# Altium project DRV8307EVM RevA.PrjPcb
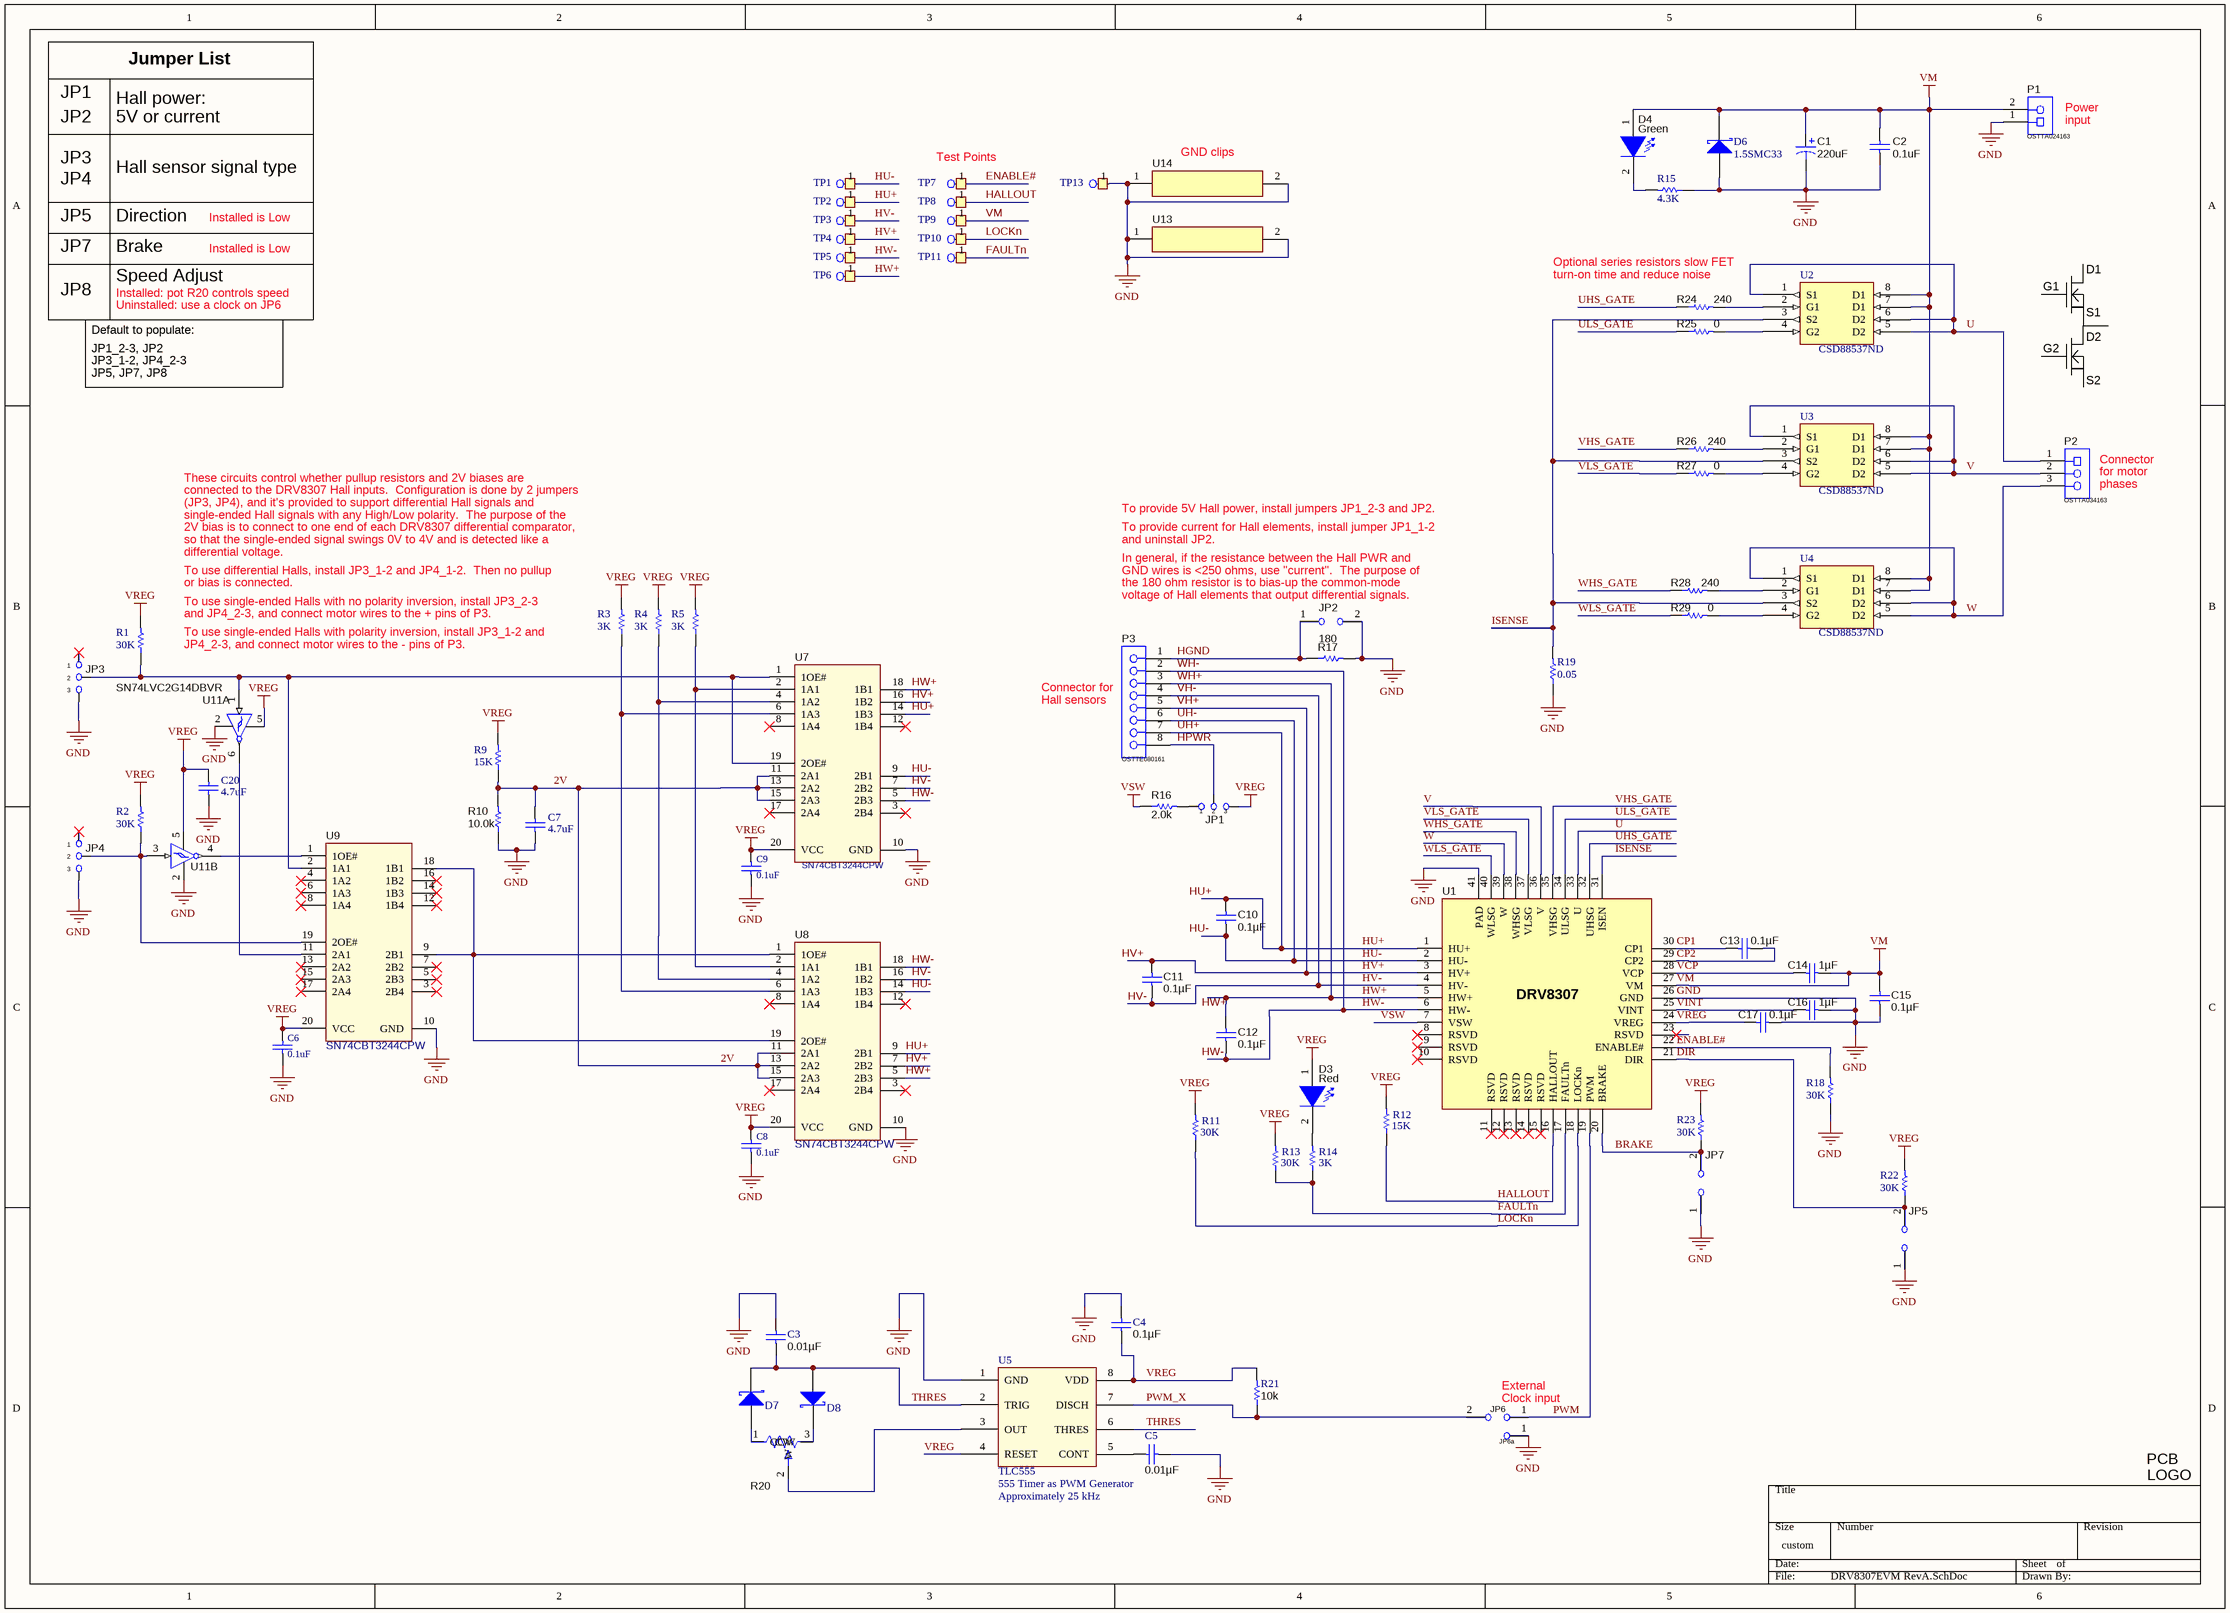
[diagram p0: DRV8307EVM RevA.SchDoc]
CopyrightYear: 2012; PCB_Layout: Who did the Layout?; PCB_Rev: E1; PRJ_Customer: Public Release; PRJ_Engineer: Enter name of project lead; PRJ_Number: XX####; PRJ_Title: Change in menu Project|Project Options|Parameters; SCH_Rev: E1; TechSupport: http://www.ti.com/support
1 sheet, 84 parts. Net scope: global (net labels, ports and power ports of the same name join across sheets).
Board file: DRV8307EVM RevA.PcbDoc

## Sheet DRV8307EVM RevA.SchDoc
size 457 x 330 mm

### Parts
C1  220uF  [UVZ1J221MPD_fp]
C2  ValueDisplayed: 0.1uF  [0805L]  (hidden comment: 06031C272JAT2A)
C3  ValueDisplayed: 0.01µF  [0805L]  (hidden comment: GRM155R61A103KA01D)
C4  ValueDisplayed: 0.1µF  [0805L]  (hidden comment: C1005X5R1A104K)
C5  ValueDisplayed: 0.01µF  [0805L]  (hidden comment: GRM155R61A103KA01D)
C6  value 0.1uF  [0805L]  (hidden comment: Cap)
C7  value 4.7uF  [0805L]
C8  value 0.1uF  [0805L]  (hidden comment: Cap)
C9  value 0.1uF  [0805L]  (hidden comment: Cap)
C10  ValueDisplayed: 0.1µF  [0805L]  (hidden comment: C0805C104K5RACTU)
C11  ValueDisplayed: 0.1µF  [0805L]  (hidden comment: C0805C104K5RACTU)
C12  ValueDisplayed: 0.1µF  [0805L]  (hidden comment: C0805C104K5RACTU)
C13  ValueDisplayed: 0.1µF  [0805L]  (hidden comment: C0805C104K5RACTU)
C14  ValueDisplayed: 1µF  [0805L]  (hidden comment: C0805C104K5RACTU)
C15  ValueDisplayed: 0.1µF  [0805L]  (hidden comment: C0805C104K5RACTU)
C16  ValueDisplayed: 1µF  [0805L]  (hidden comment: C0805C104K5RACTU)
C17  ValueDisplayed: 0.1µF  [0805L]  (hidden comment: C0805C104K5RACTU)
C20  value 4.7uF  [0805L]
D3  value Red  [LED_LTST-C170]  (hidden comment: LTST-C170KRKT)
D4  value Green  [LED_LTST-C171]  (hidden comment: LTST-C171GKT)
D6  1.5SMC33  [SMC-W]
D7  MBRA210LT3G  [SMA]  (value not drawn)
D8  MBRA210LT3G  [SMA]  (value not drawn)
JP1  Pin1: 1  Pin2: 2  Pin3: 3  [HDR100_1X3]  (hidden comment: JUMPER_3X100MIL)
JP2  JUMPER_2X100MIL  [2PIN HEADER]  (value not drawn)
JP3  Pin1: 1  Pin2: 2  Pin3: 3  [HDR100_1X3]  (hidden comment: JUMPER_3X100MIL)
JP4  Pin1: 1  Pin2: 2  Pin3: 3  [HDR100_1X3]  (hidden comment: JUMPER_3X100MIL)
JP5  (no value)  [HDR100_1X2]
JP6  (no value)  [HDR100_1X2]
JP6a  (no value)  [1x1 Header]
JP7  (no value)  [HDR100_1X2]
LOGO  Texas Instruments  [TI_Stacked_Overlay_Medium]  (value not drawn)  (no BOM)
P1  OSTTA024163  [On-Shore_OSTTA024163]
P2  OSTTA034163  [On-Shore_OSTTA034163]
P3  OSTTE080161  [On-Shore_OSTTE080161]
R1  value 30K  [0805L]
R2  value 30K  [0805L]
R3  value 3K  [0805L]
R4  value 3K  [0805L]
R5  value 3K  [0805L]
R9  value 15K  [0805L]
R10  value 10.0k  [0805L]  (hidden comment: RT0805BRD0710KL)
R11  30K  [0805l]
R12  15K  [0805L]
R13  30K  [0805L]
R14  3K  [0805L]
R15  value 4.3K  [0805L]  (hidden comment: Res1)
R16  value 2.0k  [0805_HV]  (hidden comment: ERJ-6GEYJ202V)
R17  value 180  [0805L]  (hidden comment: CRCW0805180RJNEA)
R18  value 30K  [0805L]
R19  value 0.05  [2512M]
R20  3352T-1-502LF  [3352_Trimmer_Pot]  (value not drawn)
R21  value 10k  [0805L]  (hidden comment: CRCW040210K0JNED)
R22  value 30K  [0805L]
R23  value 30K  [0805L]
R24  value 240  [0603L]  (hidden comment: RC0603FR-07240RL)
R25  value 0  [0603L]  (hidden comment: RC0603FR-07240RL)
R26  value 240  [0603L]  (hidden comment: RC0603FR-07240RL)
R27  value 0  [0603L]  (hidden comment: RC0603FR-07240RL)
R28  value 240  [0603L]  (hidden comment: RC0603FR-07240RL)
R29  value 0  [0603L]  (hidden comment: RC0603FR-07240RL)
TP1  TP-LOOP-ORANGE  [TEST POINT 0.052]  (value not drawn)
TP2  TP-LOOP-ORANGE  [TEST POINT 0.052]  (value not drawn)
TP3  TP-LOOP-ORANGE  [TEST POINT 0.052]  (value not drawn)
TP4  TP-LOOP-ORANGE  [TEST POINT 0.052]  (value not drawn)
TP5  TP-LOOP-ORANGE  [TEST POINT 0.052]  (value not drawn)
TP6  TP-LOOP-ORANGE  [TEST POINT 0.052]  (value not drawn)
TP7  TP-LOOP-ORANGE  [TEST POINT 0.052]  (value not drawn)
TP8  TP-LOOP-ORANGE  [TEST POINT 0.052]  (value not drawn)
TP9  TP-LOOP-ORANGE  [TEST POINT 0.052]  (value not drawn)
TP10  TP-LOOP-BLACK  [TEST POINT 0.052]  (value not drawn)
TP11  TP-LOOP-ORANGE  [TEST POINT 0.052]  (value not drawn)
TP13  TP-LOOP-BLACK  [TEST POINT 0.052]  (value not drawn)
U1  DRV8307  [RHA0040A]
U2  CSD88537ND  [SO-8_N]
U3  CSD88537ND  [SO-8_N]
U4  CSD88537ND  [SO-8_N]
U5  TLC555  [SOIC127P600X175-8N]
U7  SN74CBT3244CPW  [PW0020A_N]
U8  SN74CBT3244CPW  [PW0020A_N]
U9  SN74CBT3244CPW  [PW0020A_N]
U11  SN74LVC2G14DBVR  [DBV0006A_N]  (parts A,B of 2)
U13  (no value)  [GND_Bridge]
U14  (no value)  [GND_Bridge]

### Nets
GND: C1.2(-) C2.2 C3.1 C4.1 C5.2 C6.1 C7.2 C8.1 C9.1 C15.2 C16.1 C17.1 C20.2 D6.1(A) JP2.2 JP3.3 JP4.3 JP5.1 JP6a.1 JP7.1 P1.1 R10.1 R15.1 R17.2 R18.1 R19.1 TP13.1 U1.26(GND) U1.41(PAD) U5.1(GND) U7.10(GND) U8.10(GND) U9.10(GND) U11.2(GND) U13.1(GND) U13.2(GND) U14.1(GND) U14.2(GND)
VM: C1.1(+) C2.1 C14.1 C15.1 D4.1(A) D6.2(K) P1.2 TP9.1 U1.27(VM) U2.7(D1) U2.8(D1) U3.7(D1) U3.8(D1) U4.7(D1) U4.8(D1)
VREG: C4.2 C6.2 C8.2 C9.2 C17.2 C20.1 D3.1(A) JP1.3 R1.2 R2.2 R3.2 R4.2 R5.2 R9.2 R11.2 R12.2 R13.2 R21.2 R22.2 R23.2 U1.24(VREG) U5.4(RESET) U5.8(VDD) U7.20(VCC) U8.20(VCC) U9.20(VCC) U11.5(VCC)
VSW: R16.1 U1.7(VSW)
2V: C7.1 R9.1 R10.2 U7.11(2A1) U7.13(2A2) U7.15(2A3) U8.11(2A1) U8.13(2A2) U8.15(2A3)
BRAKE: JP7.2 R23.1 U1.20(BRAKE)
CP1: C13.2 U1.30(CP1)
CP2: C13.1 U1.29(CP2)
DIR: JP5.2 R22.1 U1.21(DIR)
ENABLE#: R18.2 TP7.1 U1.22(ENABLE#)
FAULTn: R13.1 R14.1 TP11.1 U1.17(FAULTn)
HALLOUT: R12.1 TP8.1 U1.16(HALLOUT)
HGND: JP2.1 P3.1 R17.1
HPWR: JP1.2 P3.8
HU+: C10.1 P3.7 TP2.1 U1.1(HU+) U7.14(1B3) U8.9(2B1)  [also labelled UH+]
HU-: C10.2 P3.6 TP1.1 U1.2(HU-) U7.9(2B1) U8.14(1B3)  [also labelled UH-]
HV+: C11.1 P3.5 TP4.1 U1.3(HV+) U7.16(1B2) U8.7(2B2)  [also labelled VH+]
HV-: C11.2 P3.4 TP3.1 U1.4(HV-) U7.7(2B2) U8.16(1B2)  [also labelled VH-]
HW+: C12.1 P3.3 TP6.1 U1.5(HW+) U7.18(1B1) U8.5(2B3)  [also labelled WH+]
HW-: C12.2 P3.2 TP5.1 U1.6(HW-) U7.5(2B3) U8.18(1B1)  [also labelled WH-]
ISENSE: R19.2 U1.31(ISEN) U2.3(S2) U3.3(S2) U4.3(S2)
LOCKn: R11.1 TP10.1 U1.18(LOCKn)
PWM: JP6.1 U1.19(PWM)
PWM_X: JP6.2 R21.1 U5.7(DISCH)
THRES: C3.2 D7.1(K) D8.2(A) U5.2(TRIG) U5.6(THRES)
U: P2.1 U1.33(U) U2.1(S1) U2.5(D2) U2.6(D2)
UHS_GATE: R24.1 U1.32(UHSG)
ULS_GATE: R25.1 U1.34(ULSG)
V: P2.2 U1.36(V) U3.1(S1) U3.5(D2) U3.6(D2)
VCP: C14.2 U1.28(VCP)
VHS_GATE: R26.1 U1.35(VHSG)
VINT: C16.2 U1.25(VINT)
VLS_GATE: R27.1 U1.37(VLSG)
W: P2.3 U1.39(W) U4.1(S1) U4.5(D2) U4.6(D2)
WHS_GATE: R28.1 U1.38(WHSG)
WLS_GATE: R29.1 U1.40(WLSG)
NetC5_1: C5.1 U5.5(CONT)
NetD3_2: D3.2(K) R14.2
NetD4_2: D4.2(K) R15.2
NetD7_2: D7.2(A) R20.1(CCW)
NetD8_1: D8.1(K) R20.3(CW)
NetJP1_1: JP1.1 R16.2
NetJP3_2: JP3.2 R1.1 U7.1(1OE#) U7.19(2OE#) U9.2(1A1) U11.1(1A)
NetJP4_2: JP4.2 R2.1 U9.19(2OE#) U11.3(2A)
NetR3_1: R3.1 U7.6(1A3) U8.6(1A3)
NetR4_1: R4.1 U7.4(1A2) U8.4(1A2)
NetR5_1: R5.1 U7.2(1A1) U8.2(1A1)
NetR20_2: R20.2(W) U5.3(OUT)
NetR24_2: R24.2 U2.2(G1)
NetR25_2: R25.2 U2.4(G2)
NetR26_2: R26.2 U3.2(G1)
NetR27_2: R27.2 U3.4(G2)
NetR28_2: R28.2 U4.2(G1)
NetR29_2: R29.2 U4.4(G2)
NetU8_1: U8.1(1OE#) U8.19(2OE#) U9.9(2B1) U9.18(1B1)
NetU9_1: U9.1(1OE#) U11.4(2Y)
NetU9_11: U9.11(2A1) U11.6(1Y)

Not connected (* = marked no-connect by the designer): JP3 1*; JP4 1*; U1 8(RSVD)* 9(RSVD)* 10(RSVD)* 11(RSVD)* 12(RSVD)* 13(RSVD)* 14(RSVD)* 15(RSVD)* 23(RSVD)*; U7 3(2B4)* 8(1A4)* 12(1B4)* 17(2A4)*; U8 3(2B4)* 8(1A4)* 12(1B4)* 17(2A4)*; U9 3(2B4)* 4(1A2)* 5(2B3)* 6(1A3)* 7(2B2)* 8(1A4)* 12(1B4)* 13(2A2)* 14(1B3)* 15(2A3)* 16(1B2)* 17(2A4)*

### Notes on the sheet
- Jumper List
- JP1
- JP2
- Hall power:
- 5V or current
- (near P1) Power
- (near P1) input
- JP3
- JP4
- Hall sensor signal type
- (near TP7) Test Points
- (near U14) GND clips
- JP5
- JP7
- Direction
- Brake
- Installed is Low
- Optional series resistors slow FET
- (near R24) turn-on time and reduce noise
- D1
- JP8
- Default to populate:
- Speed Adjust
- Installed: pot R20 controls speed
- Uninstalled: use a clock on JP6
- G1
- S1
- JP1_2-3, JP2
- JP3_1-2, JP4_2-3
- JP5, JP7, JP8
- G2
- D2
- S2
- These circuits control whether pullup resistors and 2V biases are
- connected to the DRV8307 Hall inputs.  Configuration is done by 2 jumpers
- (JP3, JP4), and it's provided to support differential Hall signals and
- single-ended Hall signals with any High/Low polarity.  The purpose of the
- To provide 5V Hall power, install jumpers JP1_2-3 and JP2.
- (near P2) Connector
- (near P2) for motor
- (near P2) phases
- 2V bias is to connect to one end of each DRV8307 differential comparator,
- so that the single-ended signal swings 0V to 4V and is detected like a
- differential voltage.
- (near R3) To use differential Halls, install JP3_1-2 and JP4_1-2.  Then no pullup
- To provide current for Hall elements, install jumper JP1_1-2
- and uninstall JP2.
- In general, if the resistance between the Hall PWR and
- (near JP2) GND wires is <250 ohms, use "current".  The purpose of
- or bias is connected.
- (near R3) To use single-ended Halls with no polarity inversion, install JP3_2-3
- (near R1) and JP4_2-3, and connect motor wires to the + pins of P3.
- (near R3) To use single-ended Halls with polarity inversion, install JP3_1-2 and
- JP4_2-3, and connect motor wires to the - pins of P3.
- (near JP2) the 180 ohm resistor is to bias-up the common-mode
- (near JP2) voltage of Hall elements that output differential signals.
- (near P3) Connector for
- (near P3) Hall sensors
- (near JP6) External
- (near JP6) Clock input
- 555 Timer as PWM Generator
- Approximately 25 kHz
- Labels drawn without touching a wire or pin: HU+, HU-, HV+, HW+, HW-

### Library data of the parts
C1 = UVZ1J221MPD: SymbolVersion: use current date i.e. 2008-05-20; SymbolCreator: Use a-id; CompType: Used in some BOM reports.  Useful for finding later.; U/M: EA, IN, or GM
C2 = 06031C272JAT2A: CAP, CERM, 2700pF, 100V, +/-5%, X7R, 0603; Manufacturer: AVX; Polarized: N; CompType: Capacitor; U/M: EA; Cap_F: 0.0000000027; Tolerance_%: 5; ESR_Ohm: 0.174; Value1: 0.174 ohm; VDC_V: 100; TaMin_C: -55; TaMax_C: 125; Cap_Case: 0603
C3 C5 = GRM155R61A103KA01D: CAP, CERM, 0.01uF, 10V, +/-10%, X5R, 0402; Manufacturer: MuRata; Polarized: N; CompType: Capacitor; U/M: EA; Cap_F: 0.00000001; Tolerance_%: 10; Value1: Unknown; TaMin_C: -55; TaMax_C: 85; Cap_Case: 0402
C4 = C1005X5R1A104K: CAP, CERM, 0.1uF, 10V, +/-10%, X5R, 0402; Manufacturer: TDK; Polarized: N; CompType: Capacitor; U/M: EA; Cap_F: 0.0000001; Tolerance_%: 10; ESR_Ohm: 0.0186; Value1: 0.0186 ohm; TaMin_C: -55; TaMax_C: 85; Cap_Case: 0402
C6-C9 C20 = Cap: Capacitor
C10-C17 = C0805C104K5RACTU: CAP, CERM, 0.1uF, 50V, +/-10%, X7R, 0805; Manufacturer: Kemet; Polarized: N; CompType: Capacitor; U/M: EA; Cap_F: 0.0000001; Tolerance_%: 10; ESR_Ohm: 0.064; Value1: 0.064 ohm; VDC_V: 50; IRMS_A: 1.64; TaMin_C: -55; TaMax_C: 125; Cap_Case: 0805
D3 = LTST-C170KRKT: LED, Red, SMD; Manufacturer: Lite-On; Type: AlInGaP; Vf_V: 2; Value2: 2V; Io_A: 20; Value1: W; U/M: EA
D4 = LTST-C171GKT: LED, Green, SMD; Manufacturer: Lite-On; Type: AlInGaP; Vf_V: 2.1; Value2: 2.1V; Io_A: 20; Value1: W; U/M: EA
D6 = D Schottky: Schottky Diode
D7 D8 = MBRA210LT3G: Diode, Schottky, 10V, 2A, SMA; Manufacturer: ON Semiconductor; U/M: EA; Vf_V: 0.35; Value2: 0.35V; Io_A: 2; Vr_V: 10; TJmax_C: 125; RJC_CperW: 22
JP1 JP3 JP4 = JUMPER_3X100MIL: Header, Male 3-pin, 100mil spacing,
JP2 = JUMPER_2X100MIL: Header, Male 2-pin, 100mil spacing,
JP5-JP7 = JUMPER_2X100MIL: Header, Male 2-pin, 100mil spacing,; Manufacturer: Sullins; PartNumber: PEC02SAAN; area: 20000; Value: PEC02SAAN
JP6a = 1x1 Header
LOGO = TI_Logo: Texas Instrument Corporate Signature; SymbolCreator: a0412235
P1 = OSTTA024163: Terminal Block, 2x1, 5.08mm, TH; Manufacturer: On-Shore Technology; SymbolCreator: a0412235; U/M: EA
P2 = OSTTA034163: Terminal Block, 3x1, 5.08 mm, TH; Manufacturer: On-Shore Technology; SymbolCreator: a0412235; U/M: EA
P3 = OSTTE080161: Terminal Block, 8x1, 3.5mm, TH; Manufacturer: On-Shore Technology; SymbolCreator: a0411947; U/M: EA
R1-R5 R9 R11-R15 R18 R22 R23 = Res1: Resistor
R10 = RT0805BRD0710KL: RES, 10.0k ohm, 0.1%, 0.125W, 0805; Manufacturer: Yageo America; CompType: Resistor; Res_ohm: 10000; Value_Code: 10k0; Tolerance_%: 0.1; Power_W: 0.125; VDC_V: 150; TempCo: 25 ppm/C; EIA_Code: E192; U/M: EA
R16 = ERJ-6GEYJ202V: RES, 2.0k ohm, 5%, 0.125W, 0805; Manufacturer: Panasonic; CompType: Resistor; Res_ohm: 2000; Value_Code: 2k00; Tolerance_%: 5; Power_W: 0.125; VDC_V: 150; TempCo: 200 ppm/C; EIA_Code: E24; U/M: EA
R17 = CRCW0805180RJNEA: RES, 180 ohm, 5%, 0.125W, 0805; Manufacturer: Vishay-Dale; CompType: Resistor; Value_Code: 180R; Tolerance_%: 5; Power_W: 0.125; VDC_V: 150; TempCo: 200 ppm/C; EIA_Code: E24; U/M: EA
R19 = CSRN2512FK30L0: RES, 0.03 ohm, 1%, 2W, 2512
R20 = POT_3352P: Potentiometer, 3/8 Cermet, SingleTurn, Flat; Manufacturer: Bourns; Area: 144375; Value: {Value}
R21 = CRCW040210K0JNED: RES, 10k ohm, 5%, 0.063W, 0402; Manufacturer: Vishay-Dale; CompType: Resistor; Res_ohm: 10000; Value_Code: 10k0; Tolerance_%: 5; Power_W: 0.063; VDC_V: 50; TempCo: 200 ppm/C; EIA_Code: E24; U/M: EA
R24 R26 R28 = RC0603FR-07240RL: RES, 240 ohm, 1%, 0.1W, 0603; Manufacturer: Yageo America; CompType: Resistor; Value_Code: 240R; Tolerance_%: 1; Power_W: 0.1; VDC_V: 150; TempCo: 200 ppm/C; U/M: EA
R25 R27 R29 = RC0603FR-07240RL: RES, 240 ohm, 1%, 0.1W, 0603; Manufacturer: Yageo America; CompType: Resistor; Res_ohm: 240; Value_Code: 240R; Tolerance_%: 1; Power_W: 0.1; VDC_V: 150; TempCo: 200 ppm/C; U/M: EA
TP1-TP11 TP13 = TEST POINT: Glass Beaded Test Point
U1 = DRV8308
U2-U4 = FDS8949: MOSFET N-CH DUAL 30V 3.5A SOP8
U5 = TLC555: IC OSC MONO TIMING 2.1MHZ 8-SOIC; Manufacturer: Texas Instruments; MFG Part Number: TLC555QDR; Value: 555 Timer
U8 U9 = SN74CBT3244CPW: Manufacturer: Texas Instruments; SymbolVersion: use current date i.e. 2008-05-20; SymbolCreator: Use a-id; U/M: EA, IN, or GM
U11 = SN74LVC2G14IDBVRQ1: DUAL SCHMITT-TRIGGER INVERTER, DBV0006A; Alternate Manufacturer: None; Manufacturer: Texas Instruments; SymbolCreator: a0411947; CompType: IC; U/M: EA
U13 U14 = GND_Bridge: Manufacturer: Used in BOM report; SymbolVersion: use current date i.e. 2008-05-20; SymbolCreator: Use a-id; CompType: Used in some BOM reports.  Useful for finding later.; U/M: EA, IN, or GM

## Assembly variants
001: all parts fitted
